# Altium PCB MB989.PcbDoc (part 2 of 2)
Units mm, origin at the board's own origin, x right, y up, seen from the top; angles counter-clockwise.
Board outline 88.27 x 52.07 mm, 2 copper layers (Top Layer, Bottom Layer), stack 1.6 mm thick; 68 components, 52 nets, 227 pads, 143 vias.
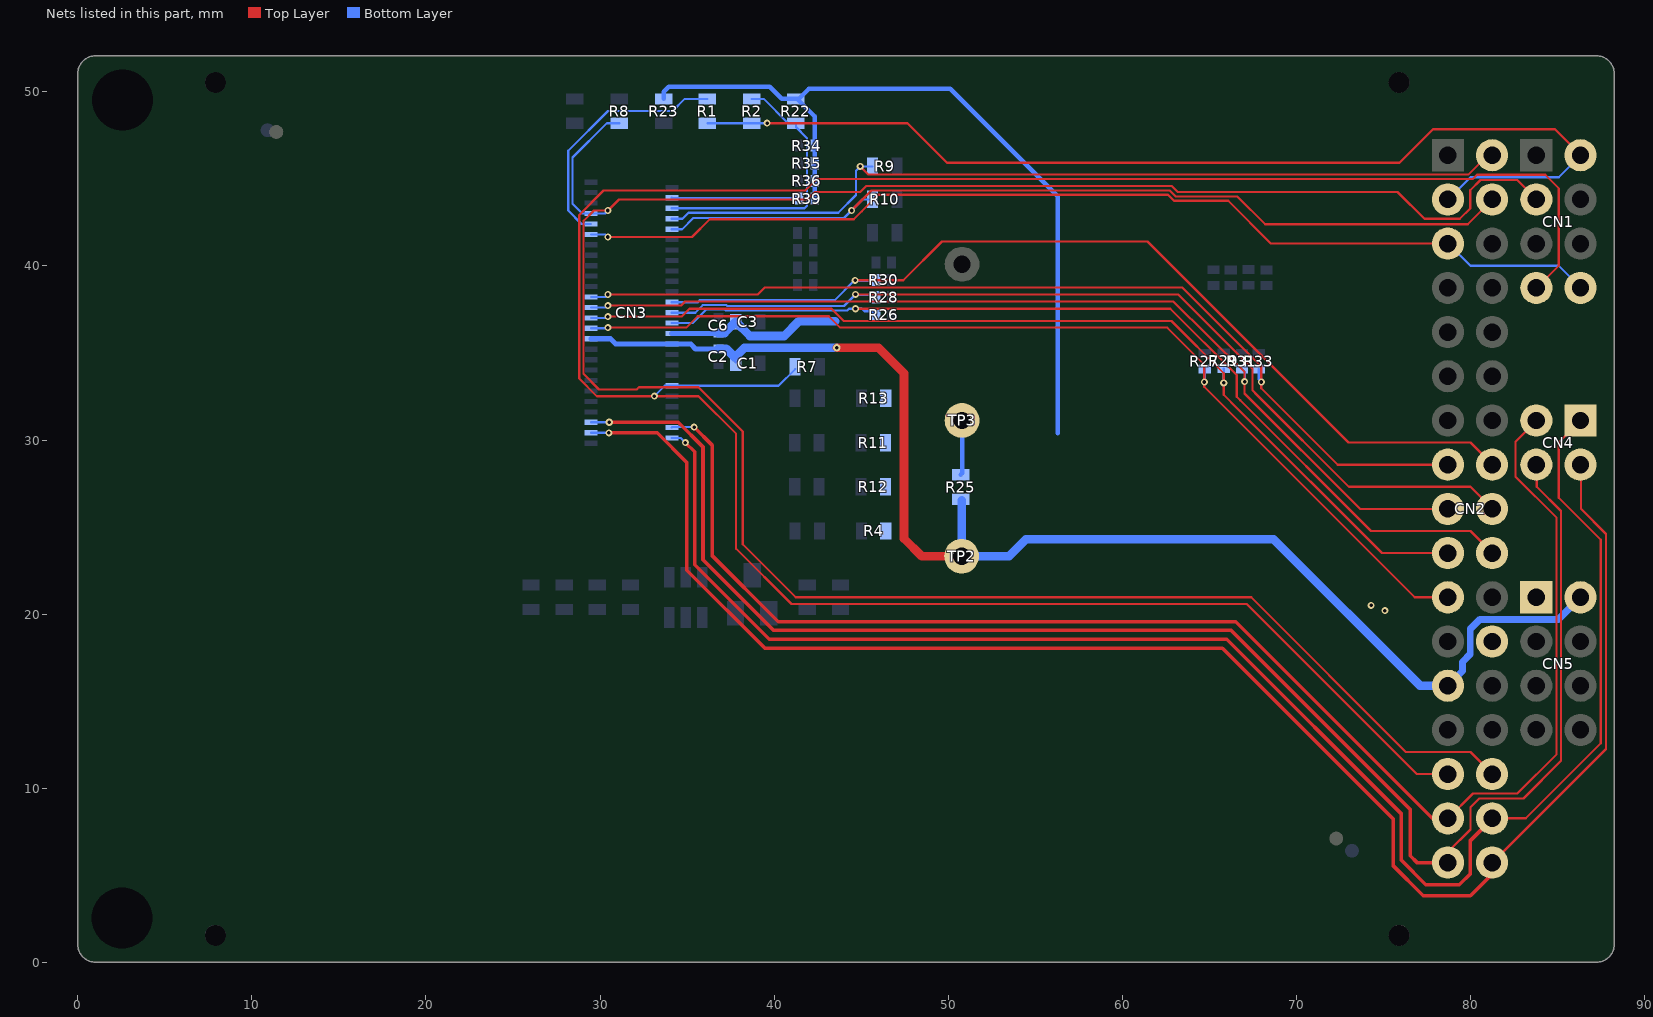
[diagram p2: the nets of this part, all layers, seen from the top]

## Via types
v1: diameter 0.406, hole 0.203, Top Layer to Bottom Layer, tented both sides, 143 vias

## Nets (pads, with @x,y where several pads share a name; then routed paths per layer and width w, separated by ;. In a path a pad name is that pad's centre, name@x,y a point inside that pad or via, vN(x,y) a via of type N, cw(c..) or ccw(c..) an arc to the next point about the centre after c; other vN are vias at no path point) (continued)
PD11: CN2.15 CN3.23 R33.2 | length 55.3
  Top Layer w0.127: v1(30.455,38.361) 39.065,38.361 39.472,38.768 63.449,38.768 67.996,34.221 v1(67.996,33.332) 67.996,32.976 72.39,28.582 CN2.15@78.715,28.582 CN2.15@78.74,28.582
  Bottom Layer w0.127: CN3.23@29.477,38.215 30.309,38.215 v1(30.455,38.361) ; R33.2@67.85,34.081 67.85,33.478 v1(67.996,33.332) v1@67.996,33.243
PD12: CN2.16 CN3.24 R30.2 | length 55.1
  Top Layer w0.127: v1(44.653,39.174) 47.422,39.174 49.648,41.4 61.452,41.4 73,29.852 80.01,29.852 CN2.16@81.28,28.582
  Bottom Layer w0.127: CN3.24@34.127,37.915 35.618,37.915 35.733,38.03 43.484,38.03 44.596,39.142 R30.2@45.854,39.142
PD13: CN2.17 CN3.25 R31.2 | length 55.8
  Top Layer w0.127: v1(30.455,37.726) 34.66,37.726 34.888,37.955 62.941,37.955 67.031,33.916 v1(67.031,33.357) 67.031,32.672 73.66,26.042 CN2.17@78.715,26.042 CN2.17@78.74,26.042
  Bottom Layer w0.127: CN3.25@29.477,37.615 30.344,37.615 v1(30.455,37.726) ; R31.2@66.878,34.076 67.05,33.904 v1@67.05,33.357
PD14: CN2.18 CN3.26 R28.2 | length 54.6
  Top Layer w0.127: v1(44.679,38.365) 63.217,38.365 67.483,34.099 67.483,32.855 67.779,32.558 73.025,27.312 80.01,27.312 CN2.18@81.28,26.042
  Bottom Layer w0.127: CN3.26@34.127,37.315 35.473,37.315 35.907,37.75 37.264,37.75 37.314,37.7 44.014,37.7 44.649,38.336 R28.2@45.847,38.336
PD15: CN2.19 CN3.27 R29.2 | length 56.8
  Top Layer w0.127: v1(30.455,37.091) 34.691,37.091 35.142,37.542 43.295,37.542 44,36.837 62.84,36.837 65.837,33.84 v1(65.837,33.281) 65.837,32.595 66.649,31.783 74.93,23.502 CN2.19@78.715,23.502 CN2.19@78.74,23.502
  Bottom Layer w0.127: CN3.27@29.477,37.015 30.379,37.015 v1(30.455,37.091) ; R29.2@65.837,34.108 65.837,33.434 v1@65.913,33.357
PD16: CN2.20 CN3.28 R26.2 | length 55.4
  Top Layer w0.127: v1(44.679,37.542) 62.77,37.542 66.581,33.731 66.581,32.487 66.788,32.279 74.295,24.772 80.01,24.772 CN2.20@81.28,23.502
  Bottom Layer w0.127: CN3.28@34.127,36.715 35.315,36.715 36.096,37.496 37.159,37.496 37.219,37.436 44.2,37.436 44.307,37.542 v1(44.679,37.542) 45.058,37.542 45.2,37.4 45.65,37.4 R26.2@45.85,37.2
PD17: CN2.21 CN3.29 R27.2 | length 57.9
  Top Layer w0.127: v1(30.455,36.456) 34.957,36.456 35.608,37.108 43.149,37.108 43.8,36.456 62.586,36.456 64.719,34.323 v1(64.719,33.332) 64.719,33.053 76.81,20.962 CN2.21@78.715,20.962 CN2.21@78.74,20.962
  Bottom Layer w0.127: CN3.29@29.477,36.415 30.414,36.415 v1(30.455,36.456) ; v1(64.719,33.332) 64.719,33.305 64.742,33.283 64.742,33.332 R27.2@64.742,34.087 R27.2@64.742,34.108
RD: CN2.4 CN3.10 R10.1 | length 50.9
  Top Layer w0.127: v1(44.45,43.187) 45.603,44.34 62.739,44.34 63.082,43.997 66.616,43.997 68.213,42.4 79.858,42.4 81.267,43.81 CN2.4@81.28,43.822
  Bottom Layer w0.127: CN3.10@34.127,42.115 34.717,42.115 35.357,42.755 44.018,42.755 v1(44.45,43.187) 45.078,43.815 45.655,43.815 R10.1@45.658,43.815
RESETn: CN1.8 CN2.5 CN3.11 | length 60.2
  Top Layer w0.127: v1(30.455,41.663) 35.281,41.663 36.297,42.679 44.577,42.679 45.035,43.137 45.984,44.086 62.634,44.086 62.977,43.743 66.094,43.743 68.555,41.282 CN2.5@78.715,41.282 CN2.5@78.74,41.282
  Bottom Layer w0.127: CN3.11@29.477,41.815 30.303,41.815 v1(30.455,41.663) ; CN2.5@78.74,41.282 80.01,40.012 85.09,40.012 86.347,38.755 CN1.8@86.36,38.742
RS: CN2.2 CN3.8 R9.1 | length 50.6
  Top Layer w0.127: v1(44.951,45.72) 45.424,45.247 79.885,45.247 80.594,45.956 80.874,45.956 81.267,46.35 CN2.2@81.28,46.362
  Bottom Layer w0.127: CN3.8@34.127,42.715 34.737,42.715 35.082,43.06 43.688,43.06 44.704,44.076 44.704,45.473 v1(44.951,45.72) 45.655,45.72 R9.1@45.658,45.72
SCL: CN3.6 R2.2 R22.1 | length 16
  Bottom Layer w0.127: CN3.6@34.127,43.315 41.751,43.315 41.885,43.449 41.885,47.353 41.257,47.981 41.257,48.202 41.257,48.205 41.25,48.205 40.803,48.205 39.408,49.601 R2.2@38.71,49.602
SDI: CN1.3 CN2.30 CN3.7 R8.1 | length 141.3
  Top Layer w0.127: CN2.30@81.28,10.802 81.267,10.815 80.01,12.072 76.302,12.072 67.412,20.962 41.25,20.962 38.202,24.01 38.202,30.487 35.662,33.027 32.233,33.027 32.106,32.9 29.947,32.9 29.058,33.789 29.058,42.596 29.649,43.187 v1(30.455,43.187) 31.09,43.822 41.91,43.822 42.339,44.251 44.951,44.251 45.294,44.594 62.844,44.594 63.187,44.251 75.822,44.251 77.366,42.707 79.403,42.707 80,43.304 80,44.346 80.592,44.938 82.705,44.938 83.807,43.835 CN1.3@83.82,43.822
  Bottom Layer w0.127: v1(30.455,43.187) 30.283,43.015 CN3.7@29.477,43.015 28.976,43.015 28.423,43.568 28.423,46.235 30.393,48.205 31.115,48.205 R8.1@31.122,48.205
SDO: CN1.7 CN2.29 CN3.40 R7.1 | length 145.2
  Top Layer w0.127: CN2.29@78.74,10.802 CN2.29@78.715,10.802 76.937,10.802 67.158,20.581 40.996,20.581 37.821,23.756 37.821,30.36 35.662,32.519 v1(33.122,32.519) 29.82,32.519 28.804,33.535 28.804,42.933 30.201,44.33 41.783,44.33 42.446,44.993 80.139,44.993 80.391,45.245 84.303,45.245 85.09,44.457 85.09,40.012 CN1.7@83.82,38.742
  Bottom Layer w0.127: v1(33.122,32.519) 33.718,33.115 CN3.40@34.127,33.115 40.256,33.115 R7.1@41.213,34.073
VCI: C1.2 C2.2 CN2.25 CN3.31 CN3.32 CN5.2 R25.2 TP2.1 | length 78.8
  Top Layer w0.5: v1(43.6,35.3) 46,35.3 47.466,33.834 47.466,24.341 48.482,23.324 TP2.1@50.775,23.324
  Bottom Layer w0.2: C1.2@37.8,34.5 C1.2@37.8,34.689 ; R25.2@50.717,26.6 R25.2@50.775,26.543
  Bottom Layer w0.3: CN3.31@29.477,35.815 30.606,35.815 30.906,35.515 CN3.32@34.127,35.515 35.213,35.515 35.492,35.236 C2.2@36.8,35.236
  Bottom Layer w0.4: CN2.25@78.715,15.882 79.554,16.722 79.554,17.254 80,17.7 80,19.14 80.56,19.7 85.073,19.7 CN5.2@86.335,20.962
  Bottom Layer w0.5: C2.2@36.8,35.236 37.253,35.236 37.8,34.689 37.8,34.8 38.3,35.3 v1(43.6,35.3) v1@43.615,35.3 ; R25.2@50.775,26.543 TP2.1@50.775,23.324 53.5,23.324 54.476,24.3 68.7,24.3 77.118,15.882 CN2.25@78.715,15.882
VDD: C3.2 C6.2 CN2.24 CN3.30 CN5.1 R4.2 R11.2 R12.2 R13.2 R22.2 R23.2 R25.1 R34.1 R35.1 R36.1 R39.1 TP3.1 | length 59.7
  Bottom Layer w0.254: R23.2@33.662,49.602 33.662,50.016 33.945,50.299 39.745,50.299 40.442,49.602 R22.2@41.25,49.602 R22.2@41.322,49.602 ; C6.2@36.765,36.115 C6.2@36.8,36.15 ; R22.2@41.257,49.602 R22.2@41.322,49.602 ; R39.1@42.327,43.695 R34.1@42.327,46.881 ; R34.1@42.335,46.921 42.335,48.59 R22.2@41.322,49.602 ; R25.1@50.717,28 50.8,28.083 TP3.1@50.8,31.122 ; 56.3,30.4 56.3,44 50.124,50.176 42.004,50.176 41.43,49.602 R22.2@41.322,49.602
  Bottom Layer w0.3: CN3.30@34.127,36.115 C6.2@36.765,36.115
  Bottom Layer w0.381: CN2.24@81.28,18.422 CN2.24@81.28,18.428 ; CN5.1@83.822,20.964 CN5.1@83.822,20.969
  Bottom Layer w0.5: C6.2@36.8,36.15 37.15,36.15 C3.2@37.8,36.8 38.622,35.978 40.578,35.978 41.418,36.818 43.5,36.818
  other v1: 75.1,20.2 74.3,20.5
VSYNC: CN3.4 R39.2 | length 7.3
  Bottom Layer w0.127: CN3.4@34.127,43.915 34.15,43.892 R39.2@41.435,43.892
WR: CN3.9 R1.2 | length 14.3
  Bottom Layer w0.127: CN3.9@29.477,42.415 28.941,42.415 28.169,43.187 28.169,46.616 30.455,48.902 34.163,48.902 34.861,49.601 R1.2@36.17,49.602
WR_SCL: CN1.2 CN2.3 R1.1 R2.1 | length 61.2
  Top Layer w0.127: v1(39.599,48.204) 47.663,48.204 49.936,45.93 75.93,45.93 77.854,47.854 84.868,47.854 86.347,46.375 CN1.2@86.36,46.362
  Bottom Layer w0.127: R1.1@36.17,48.204 38.71,48.204 v1(39.599,48.204) ; CN2.3@78.74,43.822 80.01,45.092 85.09,45.092 86.347,46.35 CN1.2@86.36,46.362
XL: CN2.31 CN3.48 CN4.2 | length 86.1
  Top Layer w0.127: CN2.31@78.74,8.262 80.162,9.685 82.702,9.685 84.963,11.945 84.963,25.534 82.6,27.897 82.6,29.902 83.807,31.11 CN4.2@83.82,31.122
  Top Layer w0.203: v1(35.408,30.741) 36.437,29.712 36.437,23.362 40.234,19.565 66.523,19.565 77.826,8.262 CN2.31@78.715,8.262 CN2.31@78.74,8.262
  Bottom Layer w0.127: CN3.48@34.127,30.715 34.153,30.741 v1(35.408,30.741)
XR: CN2.32 CN3.50 CN4.1 | length 93.9
  Top Layer w0.127: CN2.32@81.28,8.262 83.185,8.262 87.5,12.577 87.5,24.267 85.09,26.677 85.09,29.852 86.347,31.11 CN4.1@86.36,31.122
  Top Layer w0.203: v1(34.9,29.852) 35.433,29.319 35.433,22.842 39.726,18.549 66.015,18.549 76.048,8.516 76.048,5.849 77.445,4.452 79.375,4.452 80.01,5.087 80.01,6.992 81.267,8.25 CN2.32@81.28,8.262
  Bottom Layer w0.127: CN3.50@34.127,30.115 34.637,30.115 v1(34.9,29.852)
YD: CN2.33 CN3.47 CN4.4 | length 92.7
  Top Layer w0.127: CN2.33@78.74,5.722 78.74,6.357 80.01,7.627 80.01,8.897 80.518,9.405 83.058,9.405 85.217,11.564 85.217,25.915 83.82,27.312 CN4.4@83.82,28.582
  Top Layer w0.203: v1(30.531,31.021) 34.493,31.021 35.916,29.598 35.916,23.121 39.98,19.057 66.269,19.057 76.556,8.77 76.556,6.103 76.937,5.722 CN2.33@78.715,5.722 CN2.33@78.74,5.722
  Bottom Layer w0.127: CN3.47@29.477,31.015 v1@30.525,31.015
YU: CN2.34 CN3.49 CN4.3 | length 95.3
  Top Layer w0.127: v1@30.501,30.415 30.505,30.415 v1@30.51,30.415 ; CN2.34@81.28,5.722 87.8,12.242 87.8,24.602 86.36,26.042 CN4.3@86.36,28.582
  Top Layer w0.203: v1(30.505,30.411) 30.51,30.415 33.282,30.415 34.989,28.709 34.989,22.524 39.479,18.034 65.761,18.034 75.563,8.231 75.563,5.551 77.297,3.817 78.105,3.817 80.01,3.817 81.28,5.087 CN2.34@81.28,5.722
  Bottom Layer w0.127: CN3.49@29.477,30.415 v1@30.501,30.415
pads on no net: CN1.4 CN1.5 CN1.6 CN3.33 CN3.34 CN3.35 H1.1 H2.1 MIRE1.1 MIRE2.1 MIRE3.1 MIRE4.1
copper on no net: | length 0
  Bottom Layer w0.254: 28.169,35.821 28.175,35.815

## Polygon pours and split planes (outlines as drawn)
GND on Top Layer "GND" (solid, remove dead copper, pour order 404): -2.4,53.3 88.5,53.3 90.8,51 90.8,0.1 88.2,-2.5 0.1,-2.5 -3.9,1.5 -3.9,51.8
BLGND on Top Layer "TopLayer-BLGND" (hatched 90Degree grid 0.203 track 0.254, remove dead copper, pour order 388): 23.47,20.327 23.47,0.007 88.367,0.007 88.367,11.183 87.097,11.183 80.01,4.097 77.826,4.097 76.429,5.494 76.429,8.389 65.761,19.057 39.345,19.057 37.694,20.708 23.851,20.708
VDD on Top Layer "VDD" (solid, remove dead copper, pour order 384): 84.645,22.594 74.594,22.594 73.4,21.4 73.4,19.628 76.228,16.8 81.662,16.8 84.645,19.783
GND on Bottom Layer "GND" (solid, remove dead copper, pour order 402): -0.9,53.6 88.8,53.6 90.4,52 90.4,0.4 88.5,-1.5 0.5,-1.5 -2.7,1.7 -2.7,51.8
VDD on Bottom Layer "VDD" (solid, remove dead copper, pour order 390): 43,37.199 46.839,37.199 51.338,32.7 53.338,30.7 70.708,30.7 76.6,24.808 76.6,20.079 76.066,19.546 74.767,19.546 67.046,27.268 50.113,27.268 48.3,25.455 48.3,24.207 47.393,23.3 45.937,23.3 45.569,23.669 45.569,35.137 44.294,36.412 42.988,36.412 42.8,36.6 42.8,37
BLGND on Bottom Layer "BottomLayer-BLGND" (hatched 90Degree grid 0.203 track 0.254, remove dead copper, pour order 396): 24.084,20.962 33.02,20.962 33.02,19.057 34.29,17.787 34.925,17.787 34.925,13.977 44.45,4.452 76.073,4.452 78.105,2.42 85.09,2.42 85.09,12.072 83.844,12.072 83.844,16.009 86.36,16.009 86.36,20.962 81.28,20.962 81.28,23.502 88.265,23.502 88.265,0.007 23.495,0.007 23.495,20.374
BLVDD on Bottom Layer "BottomLayer-BLVDD" (hatched 90Degree grid 0.203 track 0.254, remove dead copper, pour order 392): 35.56,20.962 38.735,20.962 38.735,19.692 39.878,18.549 43.815,18.549 45.593,20.327 66.675,20.327 75.565,11.437 80.01,11.437 80.01,13.977 81.661,15.628 82.55,16.517 84.455,16.517 84.455,3.182 78.105,3.182 76.2,5.087 45.085,5.087 35.56,14.612

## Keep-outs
Keep-Out Layer:
  lines w0.127: 0,0 88.265,0.007 88.265,52.077 0,52.07 0,0 ; 5.69,45.727 cw(c6.96,45.727) 8.23,45.727 8.255,5.087 cw(c6.985,5.087) 5.715,5.087 5.69,45.727

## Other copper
Top Layer:
  text "1" at 12.3,2 h2
  text ".Layer_Name" at 19.907,-98.347 h3
  text ".GTL" at 61.602,-98.347 h3
Bottom Layer:
  text "2" at 14.159,2.032 h2
  text ".GBL" at 50.399,-98.379 h3
  text ".Layer_Name" at 91.713,-98.379 h3
Multi-Layer:
  pour cut-out: 11.9,3.6 11.9,1.6 14.5,1.6 14.5,3.6

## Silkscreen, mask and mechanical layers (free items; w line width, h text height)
TopOverlay:
  lines w0.127: 30.76,45.346 35.56,45.346 35.56,45.046 ; 30.939,29.85 35.739,29.85 35.739,30.15 ; 82.55,12.072 87.605,12.072 87.605,47.632 82.55,47.632
  text "1" at 78.613,48.267 h1.02
  text "1" at 83.566,48.267 h1.02
  text "MB989C" at 3.302,18.524 h2.1 r90
  text ".Layer_Name" at 19.907,-98.347 h3
  text ".GTO" at 61.602,-98.347 h3
BottomOverlay:
  text "E" at 75.9,43.6 h10
  text "GND" at 54.864,38.869 h0.89
  text "I" at 75,36.3 h10
  text "VDD" at 54.839,29.725 h0.89
  text "G" at 75.8,29.6 h8
  text "F" at 75.6,23.502 h10
  text "VCI" at 54.7,21.5 h0.89
  text "H" at 76.4,17.8 h10
  text "C" at 53.9,14.263 h10
  text "J" at 64.3,13.247 h13
  text "MB989C" at 75.3,12.2 h2.1
  text ".GBO" at 50.399,-98.379 h3
  text ".Layer_Name" at 91.713,-98.379 h3
TopPaste:
  text ".Layer_Name" at 19.907,-98.347 h3
  text ".GTP" at 61.602,-98.347 h3
BottomPaste:
  text ".GBP" at 50.399,-98.379 h3
  text ".Layer_Name" at 91.713,-98.379 h3
TopSolder:
  rectangle: 11.9,1.6 14.5,3.6
  text ".Layer_Name" at 19.907,-98.347 h3
  text ".GTS" at 61.602,-98.347 h3
BottomSolder:
  rectangle: 11.9,1.6 14.5,3.6
  text ".GBS" at 50.399,-98.379 h3
  text ".Layer_Name" at 91.713,-98.379 h3
M1-Board Shape:
  the board outline again, w0.127
M2-Board Dimensions:
  text ".Layer_Name" at 19.907,-98.347 h3
  text ".GM2" at 61.602,-98.347 h3
M14-Top Assembly:
  text ".Layer_Name" at 19.907,-98.347 h3
  text ".GM14" at 61.602,-98.347 h3
M15-Bottom Assembly:
  text ".GM15" at 50.399,-98.379 h3
  text ".Layer_Name" at 91.713,-98.379 h3
Drill Drawing:
  drawing of 287 lines, arcs and shapes, not listed
  text "PCB SPECIFICATIONS :" at 114.885,95.246 h3
  text "IMPEDANCE TABLE" at 4.158,93.711 h3
  text "A.   MATERIAL :" at 114.885,91.246 h3
  text "FR-4" at 153.385,91.246 h3
  text "TG-170" at 169.885,91.246 h3
  text "X  TG-150" at 188.135,91.246 h3
  text "TG-140" at 204.135,91.246 h3
  text "LAYER" at 8.408,88.711 h3
  text "TRACE" at 24.658,88.711 h3
  text "SPACING" at 35.158,88.711 h3
  text "IMPEDANCE" at 48.658,88.711 h3
  text "IMPEDANCE" at 65.658,88.711 h3
  text "TOL." at 84.408,88.711 h3
  text "B.   MATERIAL FAMILY :" at 114.885,88.246 h3
  text "N/A" at 153.385,88.246 h3
  text "(Single ended)" at 49.158,85.961 h2.5
  text "(Differentiel)" at 66.908,85.961 h2.5
  text "C.   SOLDERMASK COLOR :" at 114.885,85.246 h3
  text "GREEN" at 153.385,85.246 h3
  text "WHITE" at 169.885,85.246 h3
  text "X  BLUE" at 188.135,85.246 h3
  text "BLACK" at 204.135,85.246 h3
  text "0.127" at 26.124,82.302 h3
  text "D.   SILKSCREEN COLOR :" at 114.885,82.246 h3
  text "X  WHITE" at 153.385,82.246 h3
  text "YELLOW" at 169.885,82.246 h3
  text "BLACK" at 188.135,82.246 h3
  text "Blue ink PANTONE 2955" at 204.135,82.246 h3
  text "TOP / BOTTOM" at 3.324,82.202 h3
  text "NA" at 37.658,82.211 h3
  text "50 ohm" at 52.408,82.211 h3
  text "NA" at 68.908,82.211 h3
  text "+/- 15%" at 82.908,82.211 h3
  text "E.   SURFACE FINISH :" at 114.885,79.246 h3
  text "X  ENIG" at 153.385,79.246 h3
  text "IMMERSION SILVER" at 169.885,79.246 h3
  text "IMMERSION TIN" at 204.135,79.246 h3
  text "HASL" at 153.385,76.246 h3
  text "HASL (PB-FREE)" at 169.885,76.246 h3
  text "GOLDEN FINGER" at 204.135,76.246 h3
  text "F.   IMPEDANCE CONTROL :" at 114.885,73.246 h3
  text "NO" at 153.385,73.246 h3
  text "X  YES  (SEE IMPEDANCE TABLE FOR DETAIL INFORMATION)" at 169.885,73.246 h3
  text "G.   THROUGH VIA :" at 114.885,70.246 h3
  text "PLUG THE VIAS WHICH ARE COVERED WITH SOLDERMASK ONE OR TWO SIDE." at 153.385,70.246 h3
  text "PLUG MATERIAL :" at 153.385,67.246 h3
  text "X  SOLDERMASK" at 178.885,67.246 h3
  text "NON-CONDUCTIVE EPOXY." at 204.135,67.246 h3
  text "H.   STACK-UP :" at 114.885,64.246 h3
  text "SEE LAYER STACK-UP SEQUENCE FOR OVERALL THICKNESS." at 153.385,64.246 h3
  text "Layer" at 116.028,55.5 h2
  text "Name" at 124.401,55.5 h2
  text "Material" at 140.1,55.5 h2
  text "Thickness" at 154.654,55.5 h2
  text "Constant" at 166.609,55.5 h2
  text "Board Layer Stack" at 177.673,55.5 h2
  text "MINIMUN PARAMETERS" at 201.758,53.411 h3
  text "1" at 116.028,51.5 h2
  text "TopOverlay" at 124.401,51.5 h2
  text "DEFAULT" at 201.758,47.911 h3
  text "2" at 116.028,47.5 h2
  text "TopSolder" at 124.401,47.5 h2
  text "Solder Resist" at 140.1,47.5 h2
  text "0,010mm" at 154.654,47.5 h2
  text "3,5" at 166.609,47.5 h2
  text "3" at 116.028,43.5 h2
  text "Top Layer" at 124.401,43.5 h2
  text "Copper" at 140.1,43.5 h2
  text "0,035mm" at 154.654,43.5 h2
  text "TRACKS : 0.127 mm           / GAPS : 0.127 mm" at 201.758,42.161 h3
  text "4" at 116.028,39.5 h2
  text "Dielectric1" at 124.401,39.5 h2
  text "FR-4" at 140.1,39.5 h2
  text "1,530mm" at 154.654,39.5 h2
  text "4,8" at 166.609,39.5 h2
  text "5" at 116.028,35.5 h2
  text "Bottom Layer" at 124.401,35.5 h2
  text "Copper" at 140.1,35.5 h2
  text "0,035mm" at 154.654,35.5 h2
  text "6" at 116.028,31.5 h2
  text "BottomSolder" at 124.401,31.5 h2
  text "Solder Resist" at 140.1,31.5 h2
  text "0,010mm" at 154.654,31.5 h2
  text "3,5" at 166.609,31.5 h2
  text "7" at 116.028,27.5 h2
  text "BottomOverlay" at 124.401,27.5 h2
  text "Symbol" at 116.924,20.229 h2.4
  text "Count" at 126.322,20.229 h2.4
  text "Hole Size" at 136.1,20.229 h2.4
  text "Plated" at 155.371,20.229 h2.4
  text "Drill Layer Pair" at 163.622,20.229 h2.4
  text "Via/Pad" at 186.402,20.229 h2.4
  text "Pad Shape" at 196.245,20.229 h2.4
  text "Hole Length" at 209.103,20.229 h2.4
  text "Routed Path Length" at 222.848,20.229 h2.4
  text "2" at 126.322,16.086 h2
  text "3,500mm (137,80mil)" at 136.1,16.086 h2
  text "NPTH" at 155.371,16.086 h2
  text "Top Layer - Bottom Layer" at 163.622,16.086 h2
  text "Pad" at 186.402,16.086 h2
  text "Rounded" at 196.245,16.086 h2
  text "-" at 209.103,16.086 h2
  text "-" at 222.848,16.086 h2
  text "4" at 126.322,11.943 h2
  text "1,200mm (47,24mil)" at 136.1,11.943 h2
  text "NPTH" at 155.371,11.943 h2
  text "Top Layer - Bottom Layer" at 163.622,11.943 h2
  text "Pad" at 186.402,11.943 h2
  text "Rounded" at 196.245,11.943 h2
  text "-" at 209.103,11.943 h2
  text "-" at 222.848,11.943 h2
  text "57" at 126.322,7.8 h2
  text "1,000mm (39,37mil)" at 136.1,7.8 h2
  text "PTH" at 155.371,7.8 h2
  text "Top Layer - Bottom Layer" at 163.622,7.8 h2
  text "Pad" at 186.402,7.8 h2
  text "Rounded" at 196.245,7.8 h2
  text "-" at 209.103,7.8 h2
  text "-" at 222.848,7.8 h2
  text "143" at 126.322,3.657 h2
  text "0,203mm (8,00mil)" at 136.1,3.657 h2
  text "PTH" at 155.371,3.657 h2
  text "Top Layer - Bottom Layer" at 163.622,3.657 h2
  text "Via" at 186.402,3.657 h2
  text "Rounded" at 196.245,3.657 h2
  text "-" at 209.103,3.657 h2
  text "-" at 222.848,3.657 h2
  text "206 Total" at 126.322,-0.486 h2
  text ".Layer_Name" at 19.907,-98.347 h3
  text ".DRL" at 61.602,-98.347 h3
M20-Top Sheet Box:
  circle w0.254: c97.911,-105.068 r1.3
  region: 97.437,-97.832 81.909,-97.832 81.215,-99.607 80.004,-100.832 78.607,-98.972 78.607,-97.321 79.75,-95.924 81.186,-95.546 97.437,-95.546
  region: 83.433,-106.161 72.677,-106.161 73.671,-103.668 81.528,-103.668 81.977,-102.909 84.186,-105.457
  lines w0.254: 73.671,-103.668 82.463,-103.668 79.397,-100.131 cw(c81.2,-98.187) 81.44,-95.546 98.204,-95.546 97.442,-97.832 ; 76.985,-95.299 cw(c79.411,-96.269) 79.647,-93.667 ; 77.024,-95.266 72.677,-106.161 92,-106.161 ccw(c92.249,-103.427) 94.798,-104.447 ; 78.763,-99.201 84.186,-105.457 ; 79.017,-99.201 84.322,-105.322 ; 79.017,-98.947 84.322,-105.068 ; 79.115,-97.832 92.108,-97.832 ; 79.144,-98.82 84.449,-104.941 ; 79.271,-98.693 84.576,-104.814 ; 79.398,-98.566 84.703,-104.687 ; 79.525,-98.439 84.83,-104.56 ; 79.58,-96.487 84.885,-102.608 ; 79.649,-93.667 99.098,-93.667 94.799,-104.444 ; 79.652,-98.312 84.903,-104.37 ; 79.652,-98.058 84.957,-104.179 ; 79.652,-97.804 84.957,-103.925 ; 79.652,-96.915 84.957,-103.036 ; 79.779,-97.677 85.084,-103.798 ; 79.779,-97.296 85.084,-103.417 ; 81.151,-103.682 ccw(c81.256,-103.147) 81.554,-102.69 ; 82.238,-97.818 ccw(c82.212,-98.386) 81.881,-98.848 84.246,-101.576 cw(c82.443,-103.52) 83.175,-106.069 ; 88.519,-105.957 91.408,-97.578 ; 88.741,-105.907 91.611,-97.587 ; 88.868,-105.907 91.738,-97.587 ; 89.122,-105.907 91.992,-97.587 ; 89.376,-105.907 92.246,-97.587 ; 89.63,-105.907 92.5,-97.587 ; 89.884,-105.907 92.754,-97.587 ; 90.138,-105.907 93.008,-97.587 ; 90.392,-105.907 93.262,-97.587 ; 90.646,-105.907 93.516,-97.587 ; 90.855,-105.957 93.744,-97.578 ; 93.744,-97.832 97.437,-97.832 ; 96.768,-97.829 97.53,-95.543 ; 96.934,-97.832 97.696,-95.546 ; 97.188,-97.832 97.95,-95.546
  lines w0.3: 10.907,-110.047 100.907,-110.047 100.907,-90.047 10.907,-90.047 ; 10.907,-105.047 70.907,-105.047 ; 10.907,-100.047 70.907,-100.047 ; 10.907,-95.047 70.907,-95.047 ; 10.908,-110.047 10.908,-90.047 ; 50.907,-110.047 50.907,-95.047 ; 70.907,-110.047 70.907,-90.047 ; 88.519,-105.957 90.855,-105.957
  text "Project: '.Board_Name'" at 11.907,-93.263 h3
  text "Layer:" at 11.908,-98.347 h3
  text "Gerber:" at 51.896,-98.347 h3
  text "Variant: '.VariantName'" at 11.907,-103.347 h3
  text "Ref: MB989" at 52.023,-103.347 h3
  text "R" at 97.403,-105.83 h1.52
  text "Date: 18-OCTOBER-09" at 11.907,-108.347 h3
  text "Rev: '.Board_PCB_Revision'" at 51.966,-108.347 h3
M21-Bottom Sheet Box:
  circle w0.254: c14.09,-105.068 r1.3
  region: 28.568,-106.161 39.324,-106.161 38.331,-103.668 30.473,-103.668 30.024,-102.909 27.816,-105.457
  region: 14.565,-97.832 30.092,-97.832 30.786,-99.607 31.997,-100.832 33.394,-98.972 33.394,-97.321 32.251,-95.924 30.815,-95.546 14.565,-95.546
  lines w0.254: 14.051,-95.546 14.813,-97.832 ; 14.305,-95.546 15.067,-97.832 ; 14.471,-95.543 15.233,-97.829 ; 14.559,-97.832 13.797,-95.546 30.561,-95.546 cw(c30.801,-98.187) 32.605,-100.131 29.539,-103.668 38.331,-103.668 ; 14.565,-97.832 18.257,-97.832 ; 17.203,-104.444 12.903,-93.667 32.353,-93.667 ; 17.203,-104.447 ccw(c19.753,-103.427) 20.001,-106.161 39.324,-106.161 34.978,-95.266 ; 18.257,-97.578 21.147,-105.957 ; 18.486,-97.587 21.355,-105.907 ; 18.74,-97.587 21.609,-105.907 ; 18.994,-97.587 21.863,-105.907 ; 19.248,-97.587 22.117,-105.907 ; 19.502,-97.587 22.371,-105.907 ; 19.756,-97.587 22.625,-105.907 ; 19.893,-97.832 32.886,-97.832 ; 20.01,-97.587 22.879,-105.907 ; 20.264,-97.587 23.133,-105.907 ; 20.391,-97.587 23.26,-105.907 ; 20.593,-97.578 23.482,-105.957 ; 26.917,-103.798 32.222,-97.677 ; 26.917,-103.417 32.222,-97.296 ; 27.044,-104.179 32.349,-98.058 ; 27.044,-103.925 32.349,-97.804 ; 27.044,-103.036 32.349,-96.915 ; 27.098,-104.37 32.349,-98.312 ; 27.116,-102.608 32.421,-96.487 ; 27.171,-104.56 32.476,-98.439 ; 27.298,-104.687 32.603,-98.566 ; 27.425,-104.814 32.73,-98.693 ; 27.552,-104.941 32.857,-98.82 ; 27.679,-105.322 32.984,-99.201 ; 27.679,-105.068 32.984,-98.947 ; 27.816,-105.457 33.238,-99.201 ; 28.826,-106.069 cw(c29.559,-103.52) 27.755,-101.576 30.12,-98.848 ccw(c29.79,-98.386) 29.764,-97.818 ; 30.448,-102.69 ccw(c30.745,-103.147) 30.85,-103.682 ; 32.354,-93.667 cw(c32.591,-96.269) 35.017,-95.299
  lines w0.3: 21.147,-105.957 23.482,-105.957 ; 40.907,-110.047 40.907,-90.047 ; 40.907,-105.047 100.907,-105.047 ; 40.907,-100.047 100.907,-100.047 ; 40.907,-95.047 100.907,-95.047 ; 60.907,-110.047 60.907,-95.047 ; 10.907,-110.047 100.907,-110.047 100.907,-90.047 10.907,-90.047 10.907,-110.047
  text "Project: '.Board_Name'" at 99.713,-93.263 h3
  text "Gerber:" at 59.724,-98.347 h3
  text "Layer:" at 99.713,-98.347 h3
  text "Ref: MB989" at 59.724,-103.347 h3
  text "Variant: '.VariantName'" at 99.713,-103.347 h3
  text "R" at 14.598,-105.83 h1.52
  text "Rev: '.Board_PCB_Revision'" at 59.781,-108.347 h3
  text "Date: 18-OCTOBER-09" at 99.713,-108.347 h3

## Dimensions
0,51.07 to 88.265,51.07 on M2-Board Dimensions
1,0 to 1,52.07 on M2-Board Dimensions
